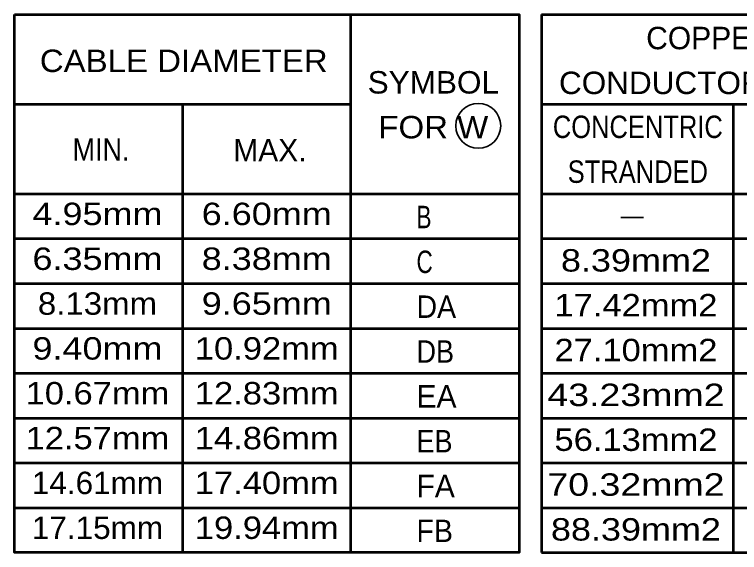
# Model space of a CAD drawing. Extents: x -32 to 824, y -6 to 538.
# Drawn here: x 519.8 to 605.1, y 357.9 to 421.3 of the extents above; entities that cross this region are included whole.
import ezdxf
from ezdxf.enums import TextEntityAlignment as Align

# ---------------------------------------------------------------- set-up
doc = ezdxf.new("R2010")
doc.units = 0
doc.header["$LTSCALE"] = 1.1
doc.layers.add('1', color=7, linetype='Continuous', lineweight=53)

msp = doc.modelspace()

# ---------------------------------------------------------------- linework, layer by layer
at = {"layer": '1'}
for p, q in [((559.369, 357.932), (559.369, 421.292)), ((581.809, 421.292), (581.809, 357.932)), ((519.769, 410.732), (559.369, 410.732)), ((539.569, 357.932), (539.569, 410.732)), ((581.809, 410.732), (621.409, 410.732)), ((604.37, 410.732), (604.37, 357.932)), ((519.769, 400.172), (579.169, 400.172)), ((581.809, 400.172), (641.209, 400.172)), ((519.769, 394.892), (579.169, 394.892)), ((581.809, 394.892), (641.209, 394.892)), ((519.769, 389.612), (579.169, 389.612)), ((581.809, 389.612), (641.209, 389.612)), ((519.769, 384.332), (579.169, 384.332)), ((581.809, 384.332), (641.209, 384.332)), ((519.769, 379.052), (579.169, 379.052)), ((581.809, 379.052), (641.209, 379.052)), ((519.769, 373.772), (579.169, 373.772)), ((581.809, 373.772), (641.209, 373.772)), ((519.769, 368.492), (579.169, 368.492)), ((581.809, 368.492), (641.209, 368.492)), ((519.769, 363.212), (579.169, 363.212)), ((581.809, 363.212), (641.209, 363.212)), ((581.809, 357.932), (641.209, 357.932))]:
    msp.add_line(p, q, dxfattribs=at)
at = {"layer": '1', "lineweight": 35}
msp.add_line((591.155, 397.368), (593.795, 397.368), dxfattribs=at)
at = {"layer": '1'}
msp.add_lwpolyline([(519.769, 421.292), (579.169, 421.292), (579.169, 357.932), (519.769, 357.932)], close=True, dxfattribs=at)
msp.add_lwpolyline([(581.809, 421.292), (641.209, 421.292), (641.209, 357.932)], dxfattribs=at)
at = {"layer": '1', "lineweight": 35}
msp.add_circle((574.36, 408.18), 2.64, dxfattribs=at)

# ---------------------------------------------------------------- texts
at = {"layer": '1'}
msp.add_text('COPPER', height=2.64, dxfattribs=at).set_placement((601.575, 417.201), align=Align.CENTER)
for s, width, p in [('CABLE DIAMETER', 1.1, (522.749, 414.516)), ('MIN.', 0.9, (526.6, 404.07)), ('B', 0.75, (567.085, 396.122)), ('C', 0.75, (567.085, 390.842)), ('DA', 0.95, (567.085, 385.562)), ('DB', 0.9, (567.085, 380.282)), ('EB', 0.9, (567.085, 369.722)), ('FB', 0.95, (567.085, 359.162))]:
    msp.add_text(s, height=2.64, dxfattribs=dict(at, width=width)).set_placement(p)
for s, width, p in [('SYMBOL', 1.05, (569.064, 411.983)), ('CONDUCTOR(AWG)', 1.05, (601.565, 411.921)), ('FOR W', 1.1, (569.064, 406.703)), ('CONCENTRIC', 0.85, (593.135, 406.743)), ('STRANDED', 0.85, (593.135, 401.463)), ('4.95mm', 1.2, (529.535, 396.49)), ('6.60mm', 1.2, (549.457, 396.49)), ('6.35mm', 1.2, (529.535, 391.21)), ('8.38mm', 1.2, (549.457, 391.21)), ('8.39mm2', 1.2, (592.914, 391.017)), ('8.13mm', 1.1, (529.535, 385.93)), ('9.65mm', 1.2, (549.457, 385.93)), ('17.42mm2', 1.15, (592.914, 385.737)), ('9.40mm', 1.2, (529.535, 380.65)), ('10.92mm', 1.15, (549.457, 380.65)), ('27.10mm2', 1.15, (592.914, 380.457)), ('10.67mm', 1.15, (529.535, 375.37)), ('12.83mm', 1.15, (549.457, 375.37)), ('43.23mm2', 1.25, (592.914, 375.177)), ('12.57mm', 1.15, (529.535, 370.09)), ('14.86mm', 1.15, (549.457, 370.09)), ('56.13mm2', 1.15, (592.914, 369.897)), ('14.61mm', 1.05, (529.535, 364.81)), ('17.40mm', 1.15, (549.457, 364.81)), ('70.32mm2', 1.25, (592.914, 364.617)), ('17.15mm', 1.05, (529.535, 359.53)), ('19.94mm', 1.15, (549.457, 359.53)), ('88.39mm2', 1.2, (592.914, 359.337))]:
    msp.add_text(s, height=2.64, dxfattribs=dict(at, width=width)).set_placement(p, align=Align.CENTER)
for s, p in [('MAX.', (545.516, 403.985)), ('EA', (567.085, 375.002)), ('FA', (567.085, 364.442))]:
    msp.add_text(s, height=2.64, dxfattribs=at).set_placement(p)

doc.saveas('drawing.dxf')
